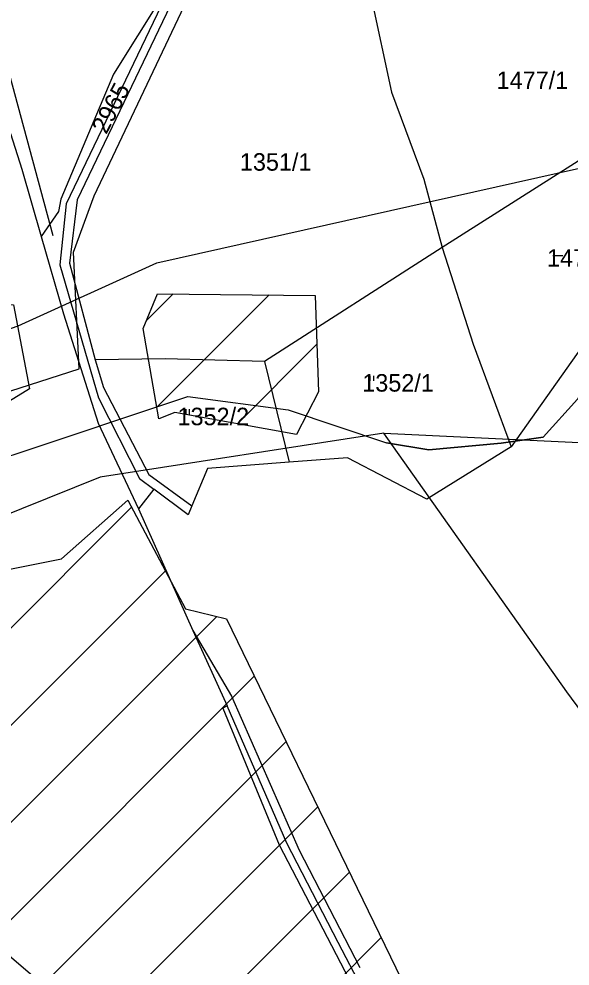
# Model space of a CAD drawing. Extents: x -564810 to -550519, y -1045831 to -1034011.
# Drawn here: x -554451.9 to -554291.4, y -1038207.3 to -1037931.5 of the extents above; entities that cross this region are included whole.
import ezdxf

# ---------------------------------------------------------------- set-up
doc = ezdxf.new("R2010")
doc.units = 0
for name, color, linetype in [('Interakční prvky', 7, 'Continuous'), ('KN stav', 7, 'Continuous'), ('Lesní porost', 7, 'Continuous'), ('Odvodněné plochy', 7, 'Continuous'), ('Parcelní čísla', 7, 'Continuous'), ('přeložka st silnice', 7, 'Continuous'), ('STG', 7, 'Continuous'), ('vodní toky', 7, 'Continuous'), ('Vrstva 33', 7, 'Continuous'), ('Vrstva 4', 7, 'Continuous'), ('zamokř ploch', 7, 'Continuous')]:
    doc.layers.add(name, color=color, linetype=linetype)

msp = doc.modelspace()

# ---------------------------------------------------------------- linework, layer by layer
at = {"layer": 'Interakční prvky'}
msp.add_line((-554479.73, -1037855.62), (-554442, -1037994.54), dxfattribs=at)
msp.add_lwpolyline([(-554500.5, -1038054.71), (-554434.35, -1038033.38), (-554435.99, -1037999.47), (-554429.98, -1037983.06), (-554380.23, -1037878.04)], dxfattribs=at)
at = {"layer": 'KN stav'}
for p, q in [((-554352.69, -1037909.76), (-554343.34, -1037952.83)), ((-554400.39, -1037912.11), (-554434.95, -1037984.21)), ((-554406.04, -1037918.35), (-554438.14, -1037985.33)), ((-554343.34, -1037952.83), (-554333.97, -1037978.2)), ((-554265.17, -1037957.75), (-554328.65, -1037998.07)), ((-554454.33, -1037964.9), (-554451.11, -1037975.3)), ((-554451.11, -1037975.3), (-554445.45, -1037994.89)), ((-554333.97, -1037978.2), (-554328.65, -1037998.07)), ((-554438.14, -1037985.33), (-554439.96, -1038003.16)), ((-554434.95, -1037984.21), (-554437.22, -1038002.62)), ((-554445.45, -1037994.89), (-554438.94, -1038017.42)), ((-554328.65, -1037998.07), (-554380.4, -1038031.3)), ((-554328.65, -1037998.07), (-554319.62, -1038026.24)), ((-554439.96, -1038003.16), (-554428.69, -1038041.89)), ((-554437.22, -1038002.62), (-554429.66, -1038030.84)), ((-554273.51, -1038006.64), (-554308.55, -1038056.16)), ((-554438.94, -1038017.42), (-554428.83, -1038049.26)), ((-554319.62, -1038026.24), (-554308.55, -1038056.16)), ((-554409.34, -1038030.47), (-554429.66, -1038030.84)), ((-554429.66, -1038030.84), (-554427.32, -1038038.88)), ((-554380.4, -1038031.3), (-554409.34, -1038030.47)), ((-554380.4, -1038031.3), (-554373.21, -1038060.63)), ((-554427.32, -1038038.88), (-554414.08, -1038064.15)), ((-554428.69, -1038041.89), (-554416.83, -1038065.32)), ((-554428.83, -1038049.26), (-554417.12, -1038074.19)), ((-554308.55, -1038056.16), (-554333.09, -1038071.38)), ((-554356.19, -1038059.36), (-554373.21, -1038060.63)), ((-554333.09, -1038071.38), (-554356.19, -1038059.36)), ((-554397.02, -1038062.4), (-554401.53, -1038073.28)), ((-554373.21, -1038060.63), (-554397.02, -1038062.4)), ((-554416.83, -1038065.32), (-554412.63, -1038068.47)), ((-554414.08, -1038064.15), (-554401.53, -1038073.28)), ((-554412.63, -1038068.47), (-554417.12, -1038074.19)), ((-554402.64, -1038075.97), (-554412.63, -1038068.47)), ((-554401.53, -1038073.28), (-554402.64, -1038075.97)), ((-554417.12, -1038074.19), (-554401.29, -1038109.64)), ((-554401.29, -1038109.64), (-554391.25, -1038131.53)), ((-554401.29, -1038109.64), (-554390, -1038128.74)), ((-554390, -1038128.74), (-554370.29, -1038173.56)), ((-554391.25, -1038131.53), (-554392.48, -1038132.27)), ((-554373.87, -1038171.53), (-554391.25, -1038131.53)), ((-554392.48, -1038132.27), (-554376.1, -1038172.04)), ((-554376.1, -1038172.04), (-554340.55, -1038240.46)), ((-554358.87, -1038200.47), (-554373.87, -1038171.53)), ((-554370.29, -1038173.56), (-554352.65, -1038207.75)), ((-554459.59, -1038200.16), (-554412.18, -1038240.63)), ((-554339.02, -1038238.68), (-554358.87, -1038200.47))]:
    msp.add_line(p, q, dxfattribs=at)
at = {"layer": 'Lesní porost'}
for p, q in [((-554549.02, -1038203.67), (-554419.08, -1038073.73)), ((-554524.38, -1038207.31), (-554409.26, -1038092.2)), ((-554501.93, -1038213.14), (-554394.29, -1038105.51)), ((-554485.74, -1038225.24), (-554383.37, -1038122.87)), ((-554468.72, -1038236.51), (-554374.11, -1038141.9)), ((-554451.39, -1038247.46), (-554364.86, -1038160.93)), ((-554434.91, -1038259.27), (-554355.61, -1038179.97)), ((-554419.08, -1038271.73), (-554346.36, -1038199))]:
    msp.add_line(p, q, dxfattribs=at)
msp.add_lwpolyline([(-554507.22, -1038209.19), (-554536.4, -1038206), (-554573.04, -1038199.24), (-554605.08, -1038189.94), (-554619.32, -1038179.63), (-554622.44, -1038172.99), (-554584.5, -1038165.15), (-554572.85, -1038152.23), (-554579.22, -1038135.83), (-554554.49, -1038128.77), (-554552.33, -1038120.34), (-554567.8, -1038103.13), (-554562.39, -1038091.06), (-554548.67, -1038083.04), (-554524.77, -1038080.2), (-554512.82, -1038072.74), (-554505.24, -1038069.15), (-554474.03, -1038095.65), (-554439.55, -1038088.79), (-554420.18, -1038071.66), (-554403.35, -1038103.31), (-554391.47, -1038106.2), (-554350.14, -1038191.22), (-554270.7, -1038354.77)], dxfattribs=at)
at = {"layer": 'Odvodněné plochy'}
for points in [[(-554508.2, -1038012.96), (-554453.45, -1038014.8), (-554448.85, -1038039.19), (-554463.12, -1038047.93), (-554495.32, -1038042.41), (-554505.44, -1038044.71)], [(-554411.59, -1038011.58), (-554365.58, -1038012.04), (-554364.66, -1038040.11), (-554371.1, -1038052.53), (-554406.53, -1038046.09), (-554411.13, -1038047.93), (-554415.73, -1038021.7)]]:
    msp.add_lwpolyline(points, close=True, dxfattribs=at)
at = {"layer": 'přeložka st silnice'}
for p, q in [((-554414.77, -1038019.37), (-554407.03, -1038011.62)), ((-554411.71, -1038044.59), (-554379.02, -1038011.9)), ((-554388.25, -1038049.42), (-554365.11, -1038026.27))]:
    msp.add_line(p, q, dxfattribs=at)
at = {"layer": 'STG'}
for points in [[(-554345.61, -1038052.13), (-554268.45, -1038055.81), (-554211.5, -1038042.95), (-554167.41, -1038052.13), (-554143.53, -1038041.11), (-554110.46, -1037952.9)], [(-554261.1, -1038169.74), (-554292.33, -1038127.48), (-554345.61, -1038052.13), (-554428.28, -1038065), (-554474.2, -1038083.37), (-554531.15, -1038105.42), (-554604.64, -1038147.69), (-554617.5, -1038151.36), (-554602.8, -1038114.61), (-554577.08, -1038083.37), (-554520.13, -1038044.78), (-554452.16, -1038020.9), (-554411.74, -1038002.52), (-554288.66, -1037974.96)]]:
    msp.add_lwpolyline(points, dxfattribs=at)
at = {"layer": 'vodní toky'}
msp.add_lwpolyline([(-554204.97, -1037993.78), (-554233.42, -1037998.93), (-554242.85, -1037995.67), (-554255.68, -1037996.82), (-554275.54, -1038020.28), (-554289.18, -1038042.25), (-554299.21, -1038053.32), (-554311.48, -1038055.08), (-554332.55, -1038057.03), (-554344.82, -1038054.97)], dxfattribs=at)
at = {"layer": 'Vrstva 33'}
msp.add_lwpolyline([(-554619.29, -1038151.54), (-554590.94, -1038120.02), (-554578.16, -1038103.54), (-554562.39, -1038091.06), (-554559.39, -1038087.71), (-554548.67, -1038083.04), (-554533.9, -1038080.78), (-554524.77, -1038080.2), (-554506.12, -1038068.17), (-554499, -1038063.96), (-554476.5, -1038063.57), (-554453.62, -1038058.43), (-554402.71, -1038041.46), (-554373.51, -1038045.38), (-554344.82, -1038054.97), (-554332.55, -1038057.03), (-554311.48, -1038055.08), (-554299.21, -1038053.32), (-554289.18, -1038042.25)], dxfattribs=at)
at = {"layer": 'Vrstva 4'}
for p, q in [((-554406.04, -1037918.35), (-554424.37, -1037947.63)), ((-554424.37, -1037947.63), (-554439.72, -1037984)), ((-554439.72, -1037984), (-554440.41, -1037987.63)), ((-554440.41, -1037987.63), (-554445.45, -1037994.89))]:
    msp.add_line(p, q, dxfattribs=at)
at = {"layer": 'zamokř ploch'}
for p, q in [((-554296.42, -1038000.42), (-554293.42, -1038000.42)), ((-554349.67, -1038035.42), (-554349.67, -1038036.92)), ((-554348.67, -1038035.42), (-554348.67, -1038036.92)), ((-554403.28, -1038045.2), (-554403.28, -1038046.7)), ((-554402.28, -1038045.2), (-554402.28, -1038046.7))]:
    msp.add_line(p, q, dxfattribs=at)

# ---------------------------------------------------------------- texts
at = {"layer": 'Parcelní čísla'}
for s, p in [('1477/1', (-554312.76, -1037951.93)), ('1351/1', (-554387.55, -1037975.71)), ('1477/2', (-554298.08, -1038003.68)), ('1352/1', (-554351.9, -1038040.05)), ('1352/2', (-554405.72, -1038049.84))]:
    msp.add_text(s, height=5.1, dxfattribs=at).set_placement(p)
msp.add_text('2965', height=5.1, rotation=62.244, dxfattribs=at).set_placement((-554426.47, -1037965.34))

doc.saveas('drawing.dxf')
